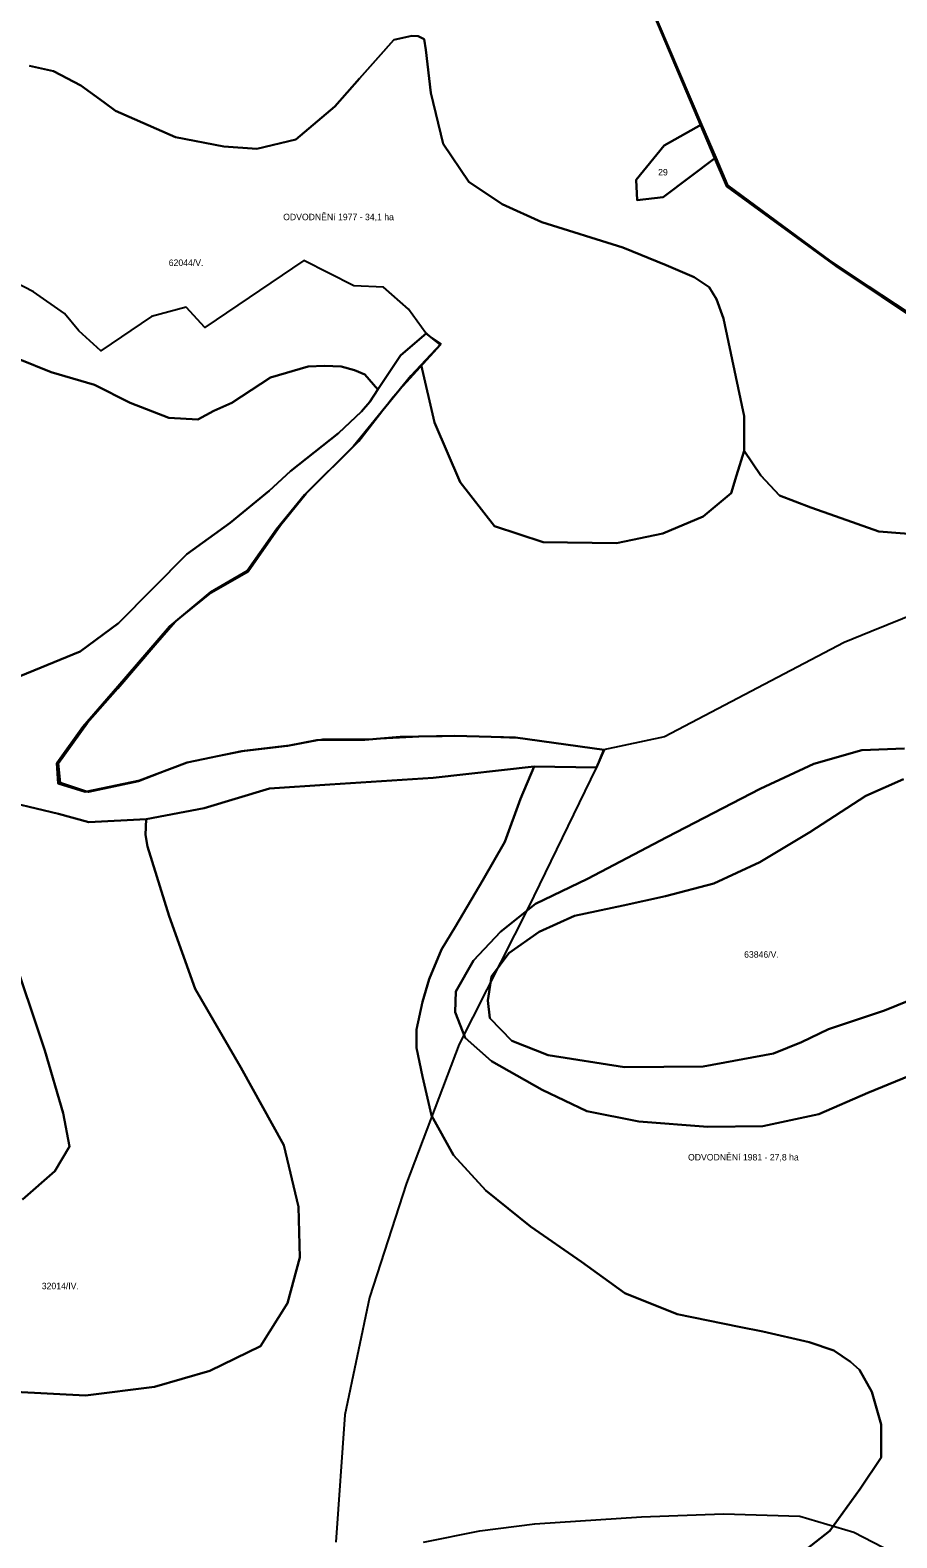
# Model space of a CAD drawing. Extents: x -521621 to -516761, y -1190184 to -1184927.
# Drawn here: x -517738 to -517203, y -1186934 to -1186003 of the extents above; entities that cross this region are included whole.
import ezdxf

# ---------------------------------------------------------------- set-up
doc = ezdxf.new("R2010")
doc.units = 0
doc.layers.add('BPEJ_s', color=7, linetype='Continuous')
doc.layers.add('odvodneni_s', color=7, linetype='Continuous')

msp = doc.modelspace()

# ---------------------------------------------------------------- linework, layer by layer
at = {"layer": 'BPEJ_s'}
for points in [[(-517010.1, -1185971.5), (-517003.7, -1186064.07), (-516996.45, -1186150.98), (-516994.45, -1186174.89), (-516993.72, -1186182.37), (-516987.52, -1186283.72), (-516982.63, -1186301.86), (-516947.67, -1186392.9), (-516936.44, -1186411.43), (-517065.71, -1186447.49), (-517155.08, -1186203.57), (-517219.62, -1186161.17), (-517243.4, -1186145.18), (-517307.11, -1186098.35), (-517314.39, -1186081.29), (-517323.17, -1186060.77), (-517357.41, -1185980.53)], [(-517357.41, -1185980.53), (-517323.17, -1186060.77), (-517346.12, -1186073.9), (-517363.45, -1186095), (-517362.87, -1186107.55), (-517346.82, -1186105.79), (-517314.39, -1186081.29), (-517307.11, -1186098.35), (-517243.4, -1186145.18), (-517219.62, -1186161.17), (-517155.08, -1186203.57)], [(-517738.12, -1186024.66), (-517723.47, -1186027.82), (-517706.57, -1186036.84), (-517692.37, -1186046.99), (-517685.08, -1186052.5), (-517648.12, -1186068.63), (-517618.11, -1186074.34), (-517597.78, -1186075.83), (-517573.72, -1186070.12), (-517549.66, -1186049.77), (-517534.29, -1186032.4), (-517522.88, -1186019.5), (-517513.21, -1186008.58), (-517502.05, -1186006.09), (-517498.08, -1186006.34), (-517494.36, -1186008.08), (-517493.32, -1186014.79), (-517490.3, -1186041.2), (-517482.76, -1186072.88), (-517466.93, -1186096.26), (-517446.23, -1186110.13), (-517421.73, -1186121.27), (-517371.76, -1186136.87), (-517345.05, -1186147.76), (-517327.73, -1186155.18), (-517318.33, -1186161.37), (-517313.88, -1186168.8), (-517309.67, -1186180.68), (-517304.23, -1186205.93), (-517296.81, -1186241.08), (-517296.81, -1186262.37), (-517301.51, -1186277.71), (-517304.86, -1186288.62), (-517322.2, -1186302.95), (-517347.08, -1186313.52), (-517375.72, -1186319.55), (-517420.95, -1186318.8), (-517451.1, -1186308.99), (-517472.21, -1186281.83), (-517488.04, -1186244.87), (-517496.31, -1186209.28), (-517484.2, -1186196.38), (-517490.27, -1186192.13), (-517493.11, -1186189.7), (-517509.15, -1186203.46), (-517523.01, -1186224.62), (-517531.1, -1186215.25), (-517537.55, -1186212.57), (-517545.7, -1186210.26), (-517556.05, -1186210.02), (-517566.15, -1186210.26), (-517589.4, -1186217.2), (-517613.25, -1186232.79), (-517624.45, -1186237.66), (-517634.19, -1186243.02), (-517652.2, -1186242.05), (-517676.05, -1186232.79), (-517697.96, -1186221.59), (-517724.74, -1186213.79), (-517745.18, -1186205.51)], [(-517189.94, -1186314.22), (-517213.69, -1186312.24), (-517240.41, -1186302.84), (-517255.74, -1186297.39), (-517275.04, -1186289.96), (-517286.42, -1186277.71), (-517296.81, -1186262.37), (-517296.81, -1186241.08), (-517304.23, -1186205.93), (-517309.67, -1186180.68), (-517313.88, -1186168.8), (-517318.33, -1186161.37), (-517327.73, -1186155.18), (-517345.05, -1186147.76), (-517371.76, -1186136.87), (-517421.73, -1186121.27), (-517446.23, -1186110.13), (-517466.93, -1186096.26), (-517482.76, -1186072.88), (-517490.3, -1186041.2), (-517493.32, -1186014.79), (-517494.36, -1186008.08), (-517498.08, -1186006.34), (-517502.05, -1186006.09), (-517513.21, -1186008.58), (-517522.88, -1186019.5), (-517534.29, -1186032.4), (-517549.66, -1186049.77), (-517573.72, -1186070.12), (-517597.78, -1186075.83), (-517618.11, -1186074.34), (-517648.12, -1186068.63), (-517685.08, -1186052.5), (-517692.37, -1186046.99), (-517706.57, -1186036.84), (-517723.47, -1186027.82), (-517738.12, -1186024.66)], [(-517764.3, -1186409.9), (-517707.01, -1186386.47), (-517683.18, -1186368.97), (-517641.06, -1186326.34), (-517614.21, -1186306.88), (-517590.12, -1186287.24), (-517577, -1186275.09), (-517547.29, -1186251.55), (-517533.17, -1186238.16), (-517527.97, -1186232.21), (-517523.01, -1186224.62), (-517509.15, -1186203.46), (-517493.11, -1186189.7), (-517490.27, -1186192.13), (-517484.2, -1186196.38), (-517496.31, -1186209.28), (-517502.72, -1186216.1), (-517538.12, -1186259.48), (-517568.42, -1186289.65), (-517585.67, -1186310.87), (-517603.75, -1186336.67), (-517626.4, -1186349.78), (-517651.79, -1186371.06), (-517683.59, -1186407.94), (-517705.32, -1186432.87), (-517721.22, -1186455.42), (-517720.43, -1186467.89), (-517703.73, -1186473.2), (-517670.34, -1186466.04), (-517640.92, -1186454.89), (-517607.26, -1186448), (-517577.84, -1186444.55), (-517560.94, -1186441.1), (-517531.12, -1186440.93), (-517509.23, -1186439.2), (-517475.61, -1186438.59), (-517437.97, -1186439.56), (-517383.38, -1186447.16), (-517388.06, -1186458.16), (-517426.51, -1186457.51), (-517488.89, -1186464.36), (-517552.65, -1186468.62), (-517589.98, -1186471.11), (-517630.35, -1186483.09), (-517666.23, -1186489.97), (-517701.52, -1186491.77), (-517720.36, -1186486.68), (-517747.87, -1186480.09)], [(-517745.18, -1186205.51), (-517724.74, -1186213.79), (-517697.96, -1186221.59), (-517676.05, -1186232.79), (-517652.2, -1186242.05), (-517634.19, -1186243.02), (-517624.45, -1186237.66), (-517613.25, -1186232.79), (-517589.4, -1186217.2), (-517566.15, -1186210.26), (-517556.05, -1186210.02), (-517545.7, -1186210.26), (-517537.55, -1186212.57), (-517531.1, -1186215.25), (-517523.01, -1186224.62), (-517527.97, -1186232.21), (-517533.17, -1186238.16), (-517547.29, -1186251.55), (-517577, -1186275.09), (-517590.12, -1186287.24), (-517614.21, -1186306.88), (-517641.06, -1186326.34), (-517683.18, -1186368.97), (-517707.01, -1186386.47), (-517764.3, -1186409.9)], [(-517269.81, -1186949.96), (-517243.89, -1186929.7), (-517225.25, -1186903.76), (-517212.29, -1186884.3), (-517212.29, -1186864.04), (-517217.96, -1186843.78), (-517225.66, -1186830.1), (-517231.13, -1186825.23), (-517241.46, -1186818.14), (-517256.64, -1186813.08), (-517285.2, -1186806.39), (-517299.98, -1186803.55), (-517338.26, -1186795.85), (-517370.46, -1186782.88), (-517397.19, -1186763.43), (-517428.78, -1186741.54), (-517456.33, -1186719.45), (-517476.38, -1186697.57), (-517489.95, -1186673.05), (-517495.41, -1186648.93), (-517499.26, -1186631.3), (-517499.26, -1186619.95), (-517495.41, -1186602.93), (-517491.36, -1186588.75), (-517483.67, -1186570.51), (-517475.16, -1186556.32), (-517458.15, -1186527.75), (-517444.58, -1186504.04), (-517434.86, -1186477.44), (-517426.51, -1186457.51), (-517388.06, -1186458.16), (-517383.38, -1186447.16), (-517437.97, -1186439.56), (-517475.61, -1186438.59), (-517509.23, -1186439.2), (-517531.12, -1186440.93), (-517560.94, -1186441.1), (-517577.84, -1186444.55), (-517607.26, -1186448), (-517640.92, -1186454.89), (-517670.34, -1186466.04), (-517703.73, -1186473.2), (-517720.43, -1186467.89), (-517721.22, -1186455.42), (-517705.32, -1186432.87), (-517683.59, -1186407.94), (-517651.79, -1186371.06), (-517626.4, -1186349.78), (-517603.75, -1186336.67), (-517585.67, -1186310.87), (-517568.42, -1186289.65), (-517538.12, -1186259.48), (-517502.72, -1186216.1), (-517496.31, -1186209.28), (-517488.04, -1186244.87), (-517472.21, -1186281.83), (-517451.1, -1186308.99), (-517420.95, -1186318.8), (-517375.72, -1186319.55), (-517347.08, -1186313.52), (-517322.2, -1186302.95), (-517304.86, -1186288.62), (-517301.51, -1186277.71), (-517296.81, -1186262.37), (-517286.42, -1186277.71), (-517275.04, -1186289.96), (-517255.74, -1186297.39), (-517240.41, -1186302.84), (-517213.69, -1186312.24), (-517189.94, -1186314.22)], [(-517172.72, -1186639.49), (-517220.35, -1186659.11), (-517250.69, -1186672.19), (-517285.24, -1186679.67), (-517319.33, -1186680.13), (-517361.81, -1186676.86), (-517394.03, -1186670.32), (-517421.57, -1186657.24), (-517452.85, -1186639.49), (-517469.2, -1186625.01), (-517475.26, -1186609.12), (-517474.8, -1186596.51), (-517464.06, -1186577.35), (-517447.25, -1186559.6), (-517425.77, -1186542.32), (-517393.56, -1186526.9), (-517344.54, -1186501.21), (-517286.91, -1186471.16), (-517253.76, -1186455.81), (-517224.08, -1186447.4), (-517197.86, -1186446.41)], [(-517197.86, -1186446.41), (-517224.08, -1186447.4), (-517253.76, -1186455.81), (-517286.91, -1186471.16), (-517344.54, -1186501.21), (-517393.56, -1186526.9), (-517425.77, -1186542.32), (-517447.25, -1186559.6), (-517464.06, -1186577.35), (-517474.8, -1186596.51), (-517475.26, -1186609.12), (-517469.2, -1186625.01), (-517452.85, -1186639.49), (-517421.57, -1186657.24), (-517394.03, -1186670.32), (-517361.81, -1186676.86), (-517319.33, -1186680.13), (-517285.24, -1186679.67), (-517250.69, -1186672.19), (-517220.35, -1186659.11), (-517172.72, -1186639.49)], [(-517747.01, -1186843.76), (-517703.63, -1186846.04), (-517661.02, -1186840.71), (-517626.77, -1186830.81), (-517595.57, -1186815.58), (-517578.83, -1186788.93), (-517571.22, -1186760.76), (-517571.98, -1186729.54), (-517581.12, -1186691.47), (-517607.75, -1186643.5), (-517635.9, -1186594.77), (-517651.88, -1186549.84), (-517665.22, -1186506.92), (-517666.57, -1186499.7), (-517666.23, -1186489.97), (-517630.35, -1186483.09), (-517589.98, -1186471.11), (-517552.65, -1186468.62), (-517488.89, -1186464.36), (-517426.51, -1186457.51), (-517434.86, -1186477.44), (-517444.58, -1186504.04), (-517458.15, -1186527.75), (-517475.16, -1186556.32), (-517483.67, -1186570.51), (-517491.36, -1186588.75), (-517495.41, -1186602.93), (-517499.26, -1186619.95), (-517499.26, -1186631.3), (-517495.41, -1186648.93), (-517489.95, -1186673.05), (-517476.38, -1186697.57), (-517456.33, -1186719.45), (-517428.78, -1186741.54), (-517397.19, -1186763.43), (-517370.46, -1186782.88), (-517338.26, -1186795.85), (-517299.98, -1186803.55), (-517285.2, -1186806.39), (-517256.64, -1186813.08), (-517241.46, -1186818.14), (-517231.13, -1186825.23), (-517225.66, -1186830.1), (-517217.96, -1186843.78), (-517212.29, -1186864.04), (-517212.29, -1186884.3), (-517225.25, -1186903.76), (-517243.89, -1186929.7), (-517269.81, -1186949.96)], [(-517163.32, -1186589.23), (-517210.08, -1186608.21), (-517244.64, -1186619.74), (-517261.43, -1186627.81), (-517278.71, -1186634.82), (-517322.13, -1186642.76), (-517370.68, -1186643.23), (-517417.84, -1186635.75), (-517440.25, -1186626.87), (-517453.79, -1186612.86), (-517455.19, -1186602.11), (-517452.85, -1186587.17), (-517442.12, -1186572.68), (-517423.44, -1186559.6), (-517401.5, -1186549.79), (-517371.62, -1186543.25), (-517345.47, -1186537.64), (-517315.59, -1186529.7), (-517287.11, -1186516.62), (-517256.3, -1186497.94), (-517221.6, -1186475.61), (-517198.35, -1186465.22)], [(-517198.35, -1186465.22), (-517221.6, -1186475.61), (-517256.3, -1186497.94), (-517287.11, -1186516.62), (-517315.59, -1186529.7), (-517345.47, -1186537.64), (-517371.62, -1186543.25), (-517401.5, -1186549.79), (-517423.44, -1186559.6), (-517442.12, -1186572.68), (-517452.85, -1186587.17), (-517455.19, -1186602.11), (-517453.79, -1186612.86), (-517440.25, -1186626.87), (-517417.84, -1186635.75), (-517370.68, -1186643.23), (-517322.13, -1186642.76), (-517278.71, -1186634.82), (-517261.43, -1186627.81), (-517244.64, -1186619.74), (-517210.08, -1186608.21), (-517163.32, -1186589.23)], [(-517747.87, -1186480.09), (-517720.36, -1186486.68), (-517701.52, -1186491.77), (-517666.23, -1186489.97), (-517666.57, -1186499.7), (-517665.22, -1186506.92), (-517651.88, -1186549.84), (-517635.9, -1186594.77), (-517607.75, -1186643.5), (-517581.12, -1186691.47), (-517571.98, -1186729.54), (-517571.22, -1186760.76), (-517578.83, -1186788.93), (-517595.57, -1186815.58), (-517626.77, -1186830.81), (-517661.02, -1186840.71), (-517703.63, -1186846.04), (-517747.01, -1186843.76)], [(-517742.44, -1186724.97), (-517722.65, -1186707.46), (-517713.52, -1186692.23), (-517717.33, -1186671.67), (-517728.74, -1186632.84), (-517750.05, -1186568.88)], [(-517750.05, -1186568.88), (-517728.74, -1186632.84), (-517717.33, -1186671.67), (-517713.52, -1186692.23), (-517722.65, -1186707.46), (-517742.44, -1186724.97)]]:
    msp.add_lwpolyline(points, dxfattribs=at)
msp.add_lwpolyline([(-517323.17, -1186060.77), (-517314.39, -1186081.29), (-517346.82, -1186105.79), (-517362.87, -1186107.55), (-517363.45, -1186095), (-517346.12, -1186073.9)], close=True, dxfattribs=at)
at = {"layer": 'odvodneni_s'}
for points in [[(-517358.73, -1185978.4), (-517323.88, -1186061.41), (-517315.26, -1186081.51), (-517315.26, -1186081.51), (-517307.69, -1186099.15), (-517240.3, -1186148.46), (-517156.28, -1186204.57)], [(-517112.03, -1186330.95), (-517218.36, -1186374.05), (-517235.08, -1186380.83), (-517345.97, -1186439.2), (-517383.7, -1186447.12), (-517411.33, -1186443.42), (-517436.4, -1186439.95), (-517468.66, -1186438.71), (-517497.83, -1186439.1), (-517529.62, -1186440.87), (-517557.32, -1186440.8), (-517578.92, -1186444.89), (-517606.78, -1186448.13), (-517640.88, -1186455.07), (-517670.98, -1186466.65), (-517701.69, -1186473.28), (-517718.97, -1186467.49), (-517720.21, -1186455.38), (-517702.38, -1186430.46), (-517683.56, -1186409.31), (-517660.64, -1186382.23), (-517648.14, -1186368.11), (-517625.84, -1186349.9), (-517603.15, -1186336.94), (-517583.24, -1186308.31), (-517567.27, -1186288.86), (-517534.71, -1186256.46), (-517513.57, -1186229.14), (-517484.26, -1186196.91), (-517484.26, -1186196.91), (-517490.08, -1186192.36), (-517493.51, -1186189.68), (-517504.21, -1186174.93), (-517519.54, -1186161.33), (-517537.91, -1186160.61), (-517568.71, -1186144.85), (-517629.88, -1186186.21), (-517641.45, -1186173.77), (-517662.85, -1186179.41), (-517694.23, -1186200.67), (-517707.83, -1186188.23), (-517716.65, -1186177.67), (-517735.74, -1186164.22), (-517759.02, -1186152.37)], [(-517112.03, -1186330.95), (-517218.36, -1186374.05), (-517235.08, -1186380.83), (-517345.97, -1186439.2), (-517383.7, -1186447.12), (-517388.18, -1186458.31), (-517430.14, -1186544.79), (-517472.86, -1186629.05), (-517505.29, -1186714.91), (-517528.19, -1186785.51), (-517543.45, -1186858.01), (-517548.94, -1186936.72)], [(-517494.86, -1186936.67), (-517460.04, -1186929.71), (-517426.19, -1186925.39), (-517360.16, -1186921.07), (-517309.5, -1186919.15), (-517262.43, -1186920.59), (-517229.06, -1186930.43), (-517175.45, -1186958.22)]]:
    msp.add_lwpolyline(points, dxfattribs=at)

# ---------------------------------------------------------------- texts
at = {"layer": 'BPEJ_s'}
for s, p in [('29', (-517349.95, -1186092.31)), ('62044/V.', (-517652.2, -1186148.24)), ('63846/V.', (-517296.84, -1186575.57)), ('32014/IV.', (-517730.61, -1186780.37))]:
    msp.add_text(s, height=4, dxfattribs=at).set_placement(p)
at = {"layer": 'odvodneni_s'}
for s, p in [('ODVODNĚNí 1977 - 34,1 ha', (-517581.53, -1186119.98)), ('ODVODNĚNí 1981 - 27,8 ha', (-517331.48, -1186700.83))]:
    msp.add_text(s, height=4, dxfattribs=at).set_placement(p)

doc.saveas('drawing.dxf')
